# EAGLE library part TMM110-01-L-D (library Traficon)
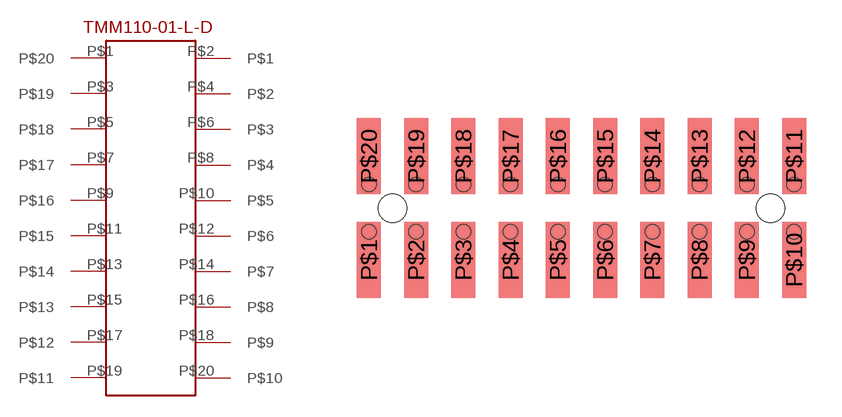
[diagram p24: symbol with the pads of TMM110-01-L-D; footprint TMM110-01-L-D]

Designator prefix -

## TMM110-01-L-D  [TMM110-01-L-D]
P$1  P$20
P$2  P$1
P$3  P$19
P$4  P$2
P$5  P$18
P$6  P$3
P$7  P$17
P$8  P$4
P$9  P$16
P$10  P$5
P$11  P$15
P$12  P$6
P$13  P$14
P$14  P$7
P$15  P$13
P$16  P$8
P$17  P$12
P$18  P$9
P$19  P$11
P$20  P$10

## Footprint TMM110-01-L-D (pad centres in mm)
smd 1.016 x 3.213: P$1 -9,-2.2; P$2 -7,-2.2; P$3 -5,-2.2; P$4 -3,-2.2; P$5 -1,-2.2; P$6 1,-2.2; P$7 3,-2.2; P$8 5,-2.2; P$9 7,-2.2; P$10 9,-2.2; P$11 9,2.2; P$12 7,2.2; P$13 5,2.2; P$14 3,2.2; P$15 1,2.2; P$16 -1,2.2; P$17 -3,2.2; P$18 -5,2.2; P$19 -7,2.2; P$20 -9,2.2
hole 1.2 at -8,0
hole 1.2 at 8,0
hole 0.6 at -9,1
hole 0.6 at -7,1
hole 0.6 at -5,1
hole 0.6 at -3,1
hole 0.6 at -1,1
hole 0.6 at 1,1
hole 0.6 at 3,1
hole 0.6 at 5,1
hole 0.6 at 7,1
hole 0.6 at 9,1
hole 0.6 at -9,-1
hole 0.6 at -7,-1
hole 0.6 at -5,-1
hole 0.6 at -3,-1
hole 0.6 at -1,-1
hole 0.6 at 1,-1
hole 0.6 at 3,-1
hole 0.6 at 5,-1
hole 0.6 at 7,-1
hole 0.6 at 9,-1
